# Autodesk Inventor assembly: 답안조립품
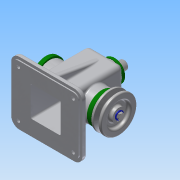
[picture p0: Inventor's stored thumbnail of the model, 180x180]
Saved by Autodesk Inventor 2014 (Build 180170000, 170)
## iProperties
Created: 2015-12
Part Number: 답안조립품
Document SubType Name: Assembly
Designer: Administrator
Author: Administrator
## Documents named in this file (19)
- D:\451225V1019\답안조립품.iam
- D:\451225V1019\본체.ipt
- D:\451225V1019\편심축.ipt
- D:\451225V1019\키 5 x 5 x 14.ipt
- D:\451225V1019\볼트 M6 x 12.ipt
- D:\451225V1019\와셔.ipt
- D:\451225V1019\V-벨트풀리.ipt
- D:\451225V1019\베어링 15 x 35 x 11.ipt
- D:\451225V1019\멈춤링 15 x 1.ipt
- D:\451225V1019\뒤커버.ipt
- D:\451225V1019\볼트 M4 x 10.ipt
- D:\451225V1019\앞커버.ipt
- D:\451225V1019\오일실 15 25 7.ipt
- D:\451225V1019\상부부시.ipt
- D:\451225V1019\슬라이드바.ipt
- D:\451225V1019\고정핀.ipt
- D:\451225V1019\링크.ipt
- D:\451225V1019\멈춤링 6 x 5.ipt
- D:\451225V1019\볼트 M3 x 8.ipt
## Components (15 placed, 5 different names)
1. ISO 4018 M6 x 12:1
2. V-벨트풀리:1
3. 고정핀:1
4. ISO 4762 M4 x 10:2
5. ISO 4762 M4 x 10:3
6. ISO 4762 M4 x 10:4
7. ISO 4762 M4 x 10:5
8. ISO 4762 M4 x 10:1
9. ISO 4762 M4 x 10:6
10. ISO 4762 M4 x 10:7
11. ISO 4762 M4 x 10:8
12. ISO 4762 M3 x 8:1
13. ISO 4762 M3 x 8:2
14. ISO 4762 M3 x 8:3
15. ISO 4762 M3 x 8:4
